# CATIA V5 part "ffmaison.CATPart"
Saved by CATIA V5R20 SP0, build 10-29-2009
Part number: Pièce1
Bounding box of the stored display mesh (mm): x -800 to 800, y -110 to 1752.311, z -20 to 730.719
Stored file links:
  C:\Users\bensf\Desktop\bouthaina\ffmaison.CATPart
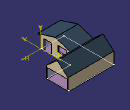
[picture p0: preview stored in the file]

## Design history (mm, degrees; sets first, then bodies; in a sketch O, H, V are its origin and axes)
Body1 (main body)
  Sketch1 on yz-plane, origin (0, 0, 0), H (0, 1, 0), V (0, 0, 1)
    line L1 (0, 0) -> (1000, 0)
    line L2 (0, 0) -> (0, 400)
    line L3 (1000, 0) -> (1000, 400)
    line L4 (0, 400) -> (-110, 400)
    line L5 (-110, 400) -> (500, 593.6492)
    line L6 (500, 593.6492) -> (1110, 400)
    line L7 (1110, 400) -> (1000, 400)
    length L1 = 1000
    length L3 = 400
    length L2 = 400
    length L5 = 640
    length L6 = 640
    length L4 = 110
    length L7 = 110
    horizontal: L1 H, L4 H, L7 H
    vertical: L2 V, L3 V
  Pad1: profile Sketch1, direction (-1, 0, 0), length 800
  Sketch2 on start face of Pad1, origin (0, 0, 0), H (0, 1, 0), V (0, 0, 1)
    line L1 (1000, 400) -> (1750, 400)
    line L2 (1750, 400) -> (1750, 0)
    line L3 (1750, 0) -> (1000, 0)
    line L4 (1000, 0) -> (1000, 400)
    point P3 (1750, 0)
    reference projected line E1 (1000, 0) -> (1000, 400) from edge [face of Pad1 from Sketch1.L3 | start face of Pad1]
    length L2 = 400
    length L1 = 750
    horizontal: L1 H, L3 H
    vertical: L2 V, L4 V
    coincidence: P3 H, L4 E1
  Pad2: profile Sketch2, direction (1, 0, 0), length 800, mirrored extent
  Sketch3 on end face of Pad2, origin (800, 0, 0), H (0, 1, 0), V (0, 0, 1)
    point P1 (1000, 400)
    line L1 (1000, 400) -> (1750, 400)
    line L2 (1750, 400) -> (1375, 730.7189)
    line L3 (1375, 730.7189) -> (1000, 400)
    reference projected point E1 (1000, 400) from vertex [face of Pad2 from Sketch2.L4 | face of Pad2 from Sketch2.L1 | end face of Pad2]
    length L3 = 500
    length L2 = 500
    length L1 = 750
    horizontal: L1 H
    coincidence: P1 E1
  Pad3: profile Sketch3, direction (-1, 0, 0), length 1599
  Sketch4 on face of Pad3, origin (800, 0, 0), H (0, 1, 0), V (0, 0, 1)
    point P1 (1020, 0)
    line L1 (1020, 0) -> (1730, 0)
    line L2 (1730, 0) -> (1730, 350)
    line L3 (1730, 350) -> (1020, 350)
    line L4 (1020, 350) -> (1020, 0)
    reference projected line E1 (1000, 400) -> (1000, 0) from edge [face of Pad2 from Sketch2.L4 | face of Pad3]
    reference projected line E2 (1750, 0) -> (1750, 400) from edge [face of Pad2 from Sketch2.L2 | face of Pad3]
    distance L4 E1 = 20
    distance E2 L2 = 20
    length L2 = 350
    coincidence: P1 H
    horizontal: L1 H, L3 H
    vertical: L2 V, L4 V
  Pocket1: profile Sketch4, direction (-1, 0, 0), length 1500
  Sketch5 on start face of Pad1, origin (0, 0, 0), H (0, 1, 0), V (0, 0, 1)
    point P1 (105, 0)
    line L1 (105, 0) -> (375, 0)
    line L2 (375, 0) -> (375, 360)
    line L3 (375, 360) -> (105, 360)
    line L4 (105, 360) -> (105, 0)
    reference projected line E1 (0, 400) -> (0, 0) from edge [face of Pad1 from Sketch1.L2 | start face of Pad1]
    length L4 = 360
    length L1 = 270
    distance L4 E1 = 105
    coincidence: P1 H
    horizontal: L1 H, L3 H
    vertical: L2 V, L4 V
  Pocket2: profile Sketch5, direction (-1, 0, 0), length 780
  Sketch6 on face of Pad2, origin (0, 0, 0), H (1, 0, 0), V (0, -1, 0)
    line L1 (-780, -26.7562) -> (-40, -26.7562)
    line L2 (-40, -26.7562) -> (-40, -976.7562)
    line L3 (-40, -976.7562) -> (-780, -976.7562)
    line L4 (-780, -976.7562) -> (-780, -26.7562)
    reference projected line E1 (0, 0) -> (0, -1000) from edge [face of Pad2 | start face of Pad1]
    reference projected line E2 (0, 0) -> (-800, 0) from edge [face of Pad1 from Sketch1.L2 | face of Pad2]
    reference projected line E3 (800, -1020) -> (-700, -1020) from edge [face of Pad2 | face of Pocket1 from Sketch4.L4]
    distance E1 L2 = 40
    distance L1 E2 = 26.7562
    distance L3 E3 = 43.2438
    horizontal: L1 H, L3 H
    vertical: L2 V, L4 V
  Pocket3: profile Sketch6, direction (0, 0, 1), length 405
  Sketch7 on start face of Pad1, origin (0, 0, 0), H (0, 1, 0), V (0, 0, 1)
    line L1 (600, 200) -> (900, 200)
    line L2 (900, 200) -> (900, 400)
    line L3 (900, 400) -> (600, 400)
    line L4 (600, 400) -> (600, 200)
    horizontal: L1 H, L3 H
    vertical: L2 V, L4 V
  Pocket4: profile Sketch7, direction (-1, 0, 0), length 40
  Sketch8 on face of Pocket3, origin (-780, 0, 0), H (0, 1, 0), V (0, 0, 1)
    line L1 (391.0662, 386.6376) -> (601.272, 386.6376)
    line L2 (601.272, 386.6376) -> (601.272, 209.5157)
    line L3 (601.272, 209.5157) -> (391.0662, 209.5157)
    line L4 (391.0662, 209.5157) -> (391.0662, 386.6376)
    horizontal: L1 H, L3 H
    vertical: L2 V, L4 V
  Pocket5: profile Sketch8, direction (1, 0, 0), length 42
  Sketch9 on face of Pocket5, origin (-780, 0, 0), H (0, 1, 0), V (0, 0, 1)
    line L1 (397.4996, 305.4359) -> (598.2442, 305.4359)
    line L2 (598.2442, 305.4359) -> (598.2442, 202.5547)
    line L3 (598.2442, 202.5547) -> (397.4996, 202.5547)
    line L4 (397.4996, 202.5547) -> (397.4996, 305.4359)
    horizontal: L1 H, L3 H
    vertical: L2 V, L4 V
  Pocket6: profile Sketch9, direction (1, 0, 0), length 42
  Sketch10 on face of Pocket3 from Sketch6.L1, origin (0, 26.7562, 0), H (-1, 0, 0), V (0, 0, 1)
    line L1 (200.2134, 307.1471) -> (400.1572, 307.1471)
    line L2 (400.1572, 307.1471) -> (400.1572, 194.6114)
    line L3 (400.1572, 194.6114) -> (200.2134, 194.6114)
    line L4 (200.2134, 194.6114) -> (200.2134, 307.1471)
    horizontal: L1 H, L3 H
    vertical: L2 V, L4 V
  Pad4: profile Sketch10, direction (0, 1, 0), length 42
  Sketch11 on end face of Pad4, origin (0, 68.7562, 0), H (-1, 0, 0), V (0, 0, 1)
    line L1 (222.481, 293.5074) -> (391.2191, 293.5074)
    line L2 (391.2191, 293.5074) -> (391.2191, 207.3006)
    line L3 (391.2191, 207.3006) -> (222.481, 207.3006)
    line L4 (222.481, 207.3006) -> (222.481, 293.5074)
    horizontal: L1 H, L3 H
    vertical: L2 V, L4 V
  Pocket7: profile Sketch11, direction (0, -1, 0), length 42
  Sketch12 on face of Pad2, origin (0, 0, 0), H (1, 0, 0), V (0, -1, 0)
    line L1 (-791.8029, -1752.3107) -> (776.3294, -1752.3107)
    line L2 (776.3294, -1752.3107) -> (776.3294, -1007.7247)
    line L3 (776.3294, -1007.7247) -> (-21.6961, -1007.7247)
    line L4 (-21.6961, -1007.7247) -> (-21.6961, -16.0709)
    line L5 (-21.6961, -16.0709) -> (-791.8029, -16.0709)
    line L6 (-791.8029, -16.0709) -> (-791.8029, -1752.3107)
    horizontal: L1 H, L3 H, L5 H
    vertical: L2 V, L4 V, L6 V
  Set1
    Extrude1: Element1 Sketch12, Lim1 20, Lim2 0
    Sketch13 on start face of Pad1, origin (0, 0, 0), H (0, 1, 0), V (0, 0, 1)
      circle A1 centre (421.1422, 250) radius 7.5
      point P1 (421.1422, 250)
      reference projected line E1 (1007.7247, 0) -> (16.0709, 0) from Sketch12.L4
      distance P1 E1 = 250
      radius A1 = 7.5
